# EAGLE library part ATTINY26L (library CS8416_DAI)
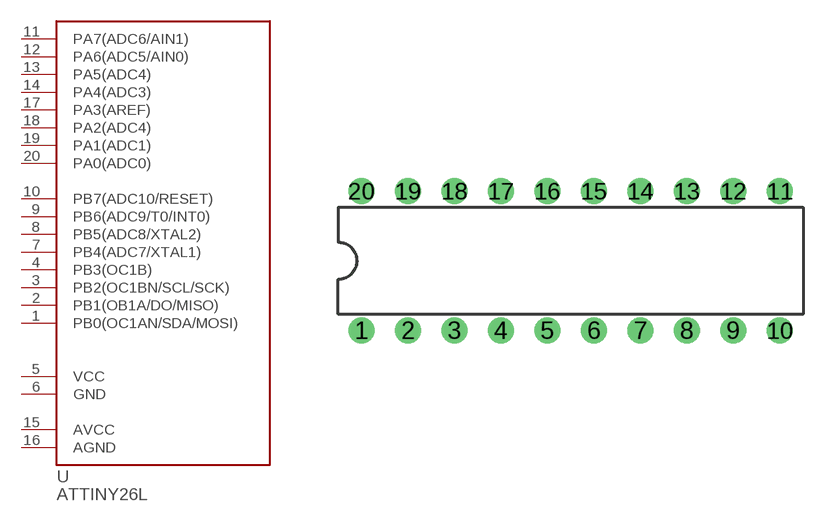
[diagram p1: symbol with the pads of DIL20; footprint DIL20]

Designator prefix U

## ATTINY26L  [DIL20]
1  PB0(OC1AN/SDA/MOSI)
2  PB1(OB1A/DO/MISO)
3  PB2(OC1BN/SCL/SCK)
4  PB3(OC1B)
5  VCC  pwr
6  GND  pwr
7  PB4(ADC7/XTAL1)
8  PB5(ADC8/XTAL2)
9  PB6(ADC9/T0/INT0)
10  PB7(ADC10/RESET)
11  PA7(ADC6/AIN1)
12  PA6(ADC5/AIN0)
13  PA5(ADC4)
14  PA4(ADC3)
15  AVCC  pwr
16  AGND  pwr
17  PA3(AREF)
18  PA2(ADC4)
19  PA1(ADC1)
20  PA0(ADC0)

## Footprint DIL20 (pad centres in mm)
Dual In Line Package
drill 0.889 round: 1 -11.43,-3.81; 2 -8.89,-3.81; 3 -6.35,-3.81; 4 -3.81,-3.81; 5 -1.27,-3.81; 6 1.27,-3.81; 7 3.81,-3.81; 8 6.35,-3.81; 9 8.89,-3.81; 10 11.43,-3.81; 11 11.43,3.81; 12 8.89,3.81; 13 6.35,3.81; 14 3.81,3.81; 15 1.27,3.81; 16 -1.27,3.81; 17 -3.81,3.81; 18 -6.35,3.81; 19 -8.89,3.81; 20 -11.43,3.81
